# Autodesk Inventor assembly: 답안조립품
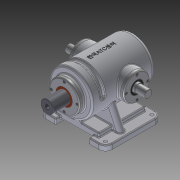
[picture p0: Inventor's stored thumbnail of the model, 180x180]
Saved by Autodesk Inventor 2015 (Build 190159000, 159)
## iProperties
Created: 2015-10
Part Number: 답안조립품
Document SubType Name: Assembly
Designer: youjin14
Mass: 9437.33 g
Surface Area: 4327.29 cm^2
Volume: 2315.26 cm^3
Density: 4.07615 g/cm^3
Author: youjin14
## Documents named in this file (13)
- C:\Users\youjin14\Desktop\351019V1009\답안조립품.iam
- C:\Users\youjin14\Desktop\351019V1009\본체.ipt
- C:\Users\youjin14\Desktop\351019V1009\슬라이드 커버.ipt
- C:\Users\youjin14\Desktop\351019V1009\부시.ipt
- C:\Users\youjin14\Desktop\351019V1009\베어링 6205.ipt
- 베어링 6205.ipt
- C:\Users\youjin14\Desktop\351019V1009\편심축.ipt
- C:\Users\youjin14\Desktop\351019V1009\축 커버.ipt
- C:\Users\youjin14\Desktop\351019V1009\가변스프링.ipt
- C:\Users\youjin14\Desktop\351019V1009\M4x0.7.ipt
- C:\Users\youjin14\Desktop\351019V1009\슬라이드.ipt
- C:\Users\youjin14\Desktop\351019V1009\오일실.ipt
- 오일실.ipt
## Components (13 placed, 2 different names)
1. 가변스프링:1 — Mate:18, Mate:20, Mate:21
2. M4x0.7:1 — Insert:1
3. M4x0.7:4
4. M4x0.7:5
5. M4x0.7:6
6. M4x0.7:2 — Insert:2
7. M4x0.7:7
8. M4x0.7:8
9. M4x0.7:9
10. M4x0.7:3 — Insert:3
11. M4x0.7:10
12. M4x0.7:11
13. M4x0.7:12
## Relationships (6: Mate 3, Insert 3)
- Mate:18: 가변스프링:1
- Insert:1: M4x0.7:1
- Insert:2: M4x0.7:2
- Insert:3: M4x0.7:3
- Mate:20: 가변스프링:1
- Mate:21: 가변스프링:1
